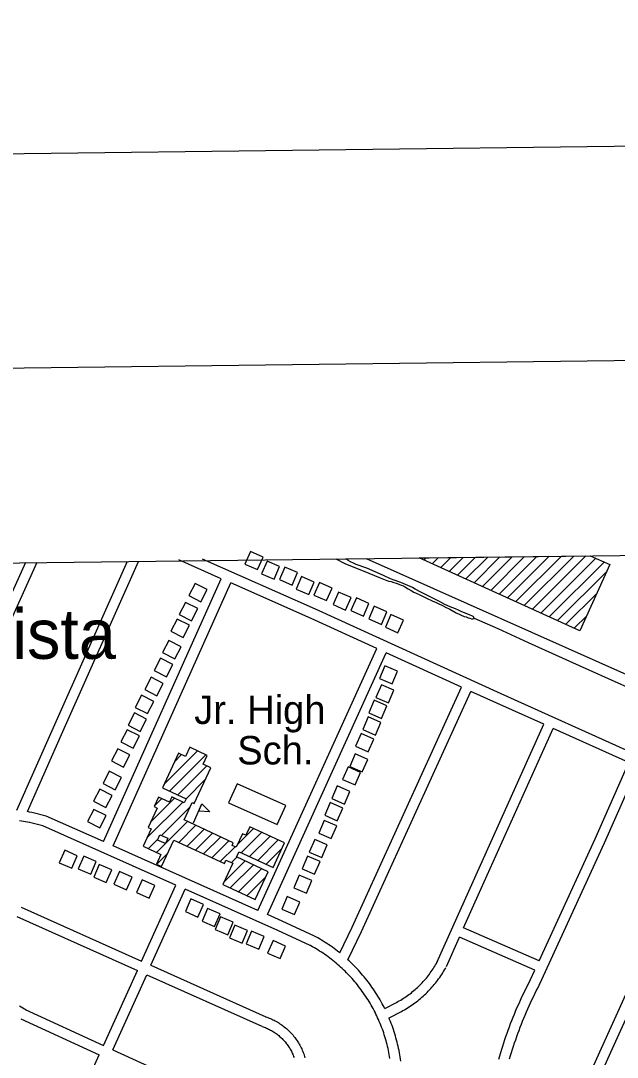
# Model space of a CAD drawing. Extents: x 3704301 to 3742427, y 506229 to 532009.
# Drawn here: x 3709792 to 3711530, y 528404 to 531426 of the extents above; entities that cross this region are included whole.
import ezdxf

# ---------------------------------------------------------------- set-up
doc = ezdxf.new("R2010")
doc.units = 0
for name, color, linetype in [('G-ANNO-NPLT', 7, 'Continuous'), ('V-ANNO-SYMB', 7, 'Continuous'), ('V-BLDG-IDEN', 7, 'Continuous'), ('V-BLDG-OTLN', 7, 'Continuous'), ('V-GRID-FRAM', 7, 'Continuous'), ('V-ROAD-CNTR', 7, 'Continuous'), ('V-TOPO-GNAM-IDEN', 7, 'Continuous'), ('V-TOPO-SHOR', 7, 'Continuous')]:
    doc.layers.add(name, color=color, linetype=linetype)

msp = doc.modelspace()

# ---------------------------------------------------------------- linework, layer by layer
at = {"layer": 'G-ANNO-NPLT'}
msp.add_lwpolyline([(3705179.5, 506812.7), (3741843.4, 507260.7), (3741548.1, 531425.5), (3704884.2, 530977.6)], close=True, dxfattribs=at)
at = {"layer": 'V-ANNO-SYMB'}
msp.add_lwpolyline([(3707921.8, 507471.3), (3741002.5, 507875.5), (3740722.5, 530790.4), (3707641.8, 530386.2), (3707921.8, 507471.3)], dxfattribs=at)
at = {"layer": 'V-BLDG-OTLN'}
for p, q in [((3710952.7, 529859.5), (3711451.3, 529865.6)), ((3711161.5, 529764.9), (3711259.8, 529863.3)), ((3711185.8, 529753.9), (3711295.6, 529863.7)), ((3711210.2, 529742.9), (3711331.4, 529864.2)), ((3711234.5, 529731.9), (3711367.2, 529864.6)), ((3711258.8, 529720.9), (3711403, 529865)), ((3711283.2, 529709.8), (3711438.8, 529865.5)), ((3710966.8, 529853.1), (3710973.5, 529859.8)), ((3710991.1, 529842.1), (3711009.3, 529860.2)), ((3711015.5, 529831.1), (3711045.1, 529860.7)), ((3711039.8, 529820.1), (3711080.8, 529861.1)), ((3711064.1, 529809), (3711116.6, 529861.5)), ((3711088.5, 529798), (3711152.4, 529862)), ((3711112.8, 529787), (3711188.2, 529862.4)), ((3711137.1, 529776), (3711224, 529862.8)), ((3711307.5, 529698.8), (3711467.1, 529858.4)), ((3711331.8, 529687.8), (3711491.4, 529847.4)), ((3711356.2, 529676.8), (3711499.3, 529819.9)), ((3711380.5, 529665.8), (3711470, 529755.3)), ((3711404.8, 529654.7), (3711440.8, 529690.7)), ((3710209.1, 529198.8), (3710307.1, 529296.8)), ((3710225.4, 529179.7), (3710331.3, 529285.6)), ((3710239.9, 529264.9), (3710260.9, 529286)), ((3710249.5, 529168.4), (3710334.2, 529253.1)), ((3710273.6, 529157.2), (3710330.5, 529214.1)), ((3710159.7, 529043.3), (3710264.2, 529147.8)), ((3710170.8, 529089.7), (3710240, 529159)), ((3710181, 529135.3), (3710203.5, 529157.8)), ((3710295.5, 529087.4), (3710320.1, 529142.1)), ((3710295.8, 529144), (3710299.7, 529148)), ((3710202.1, 529050.4), (3710285.4, 529133.6)), ((3710187.5, 529000.4), (3710278.1, 529091)), ((3710252.6, 529030.1), (3710302.2, 529079.8)), ((3710276.7, 529018.9), (3710326.4, 529068.5)), ((3710300.8, 529007.6), (3710350.5, 529057.3)), ((3710424.2, 529024.9), (3710470, 529070.8)), ((3710434.4, 528999.8), (3710494.1, 529059.5)), ((3710458.5, 528988.6), (3710518.3, 529048.3)), ((3710163.4, 529011.6), (3710191.7, 529039.9)), ((3710324.9, 528996.4), (3710374.6, 529046.1)), ((3710349.1, 528985.2), (3710398.7, 529034.8)), ((3710373.2, 528973.9), (3710416.5, 529017.2)), ((3710482.7, 528977.3), (3710542.4, 529037.1)), ((3710188.6, 528966.1), (3710219.1, 528996.6)), ((3710405.8, 528971.2), (3710421.8, 528987.2)), ((3710506.8, 528966.1), (3710552.9, 529012.3)), ((3710385, 528915), (3710446, 528976)), ((3710402.5, 528897.2), (3710470.1, 528964.8)), ((3710426.6, 528885.9), (3710494.2, 528953.5)), ((3710450.7, 528874.7), (3710507, 528930.9)), ((3710474.9, 528863.5), (3710476.2, 528864.8))]:
    msp.add_line(p, q, dxfattribs=at)
for points in [[(3710461.2, 529877.8), (3710445.2, 529841.2), (3710481.9, 529825.2), (3710497.9, 529861.8)], [(3710509.8, 529850.1), (3710493.8, 529813.4), (3710530.4, 529797.4), (3710546.4, 529834.1)], [(3710561.8, 529832.7), (3710545.8, 529796.1), (3710582.4, 529780.1), (3710598.5, 529816.7)], [(3710610.4, 529805), (3710594.3, 529768.3), (3710631, 529752.3), (3710647, 529789)], [(3710317.1, 529731.4), (3710335.5, 529766.9), (3710300, 529785.3), (3710281.6, 529749.8)], [(3710662.4, 529787.7), (3710646.4, 529751), (3710683, 529735), (3710699, 529771.7)], [(3710717.9, 529759.9), (3710701.9, 529723.3), (3710738.5, 529707.2), (3710754.5, 529743.9)], [(3710769.9, 529742.6), (3710753.9, 529705.9), (3710790.5, 529689.9), (3710806.6, 529726.6)], [(3710289.4, 529675.9), (3710307.7, 529711.5), (3710272.2, 529729.8), (3710253.8, 529694.3)], [(3710821.9, 529718.3), (3710805.9, 529681.6), (3710842.6, 529665.6), (3710858.6, 529702.3)], [(3710870.5, 529694), (3710854.5, 529657.4), (3710891.1, 529641.4), (3710907.1, 529678)], [(3710265.1, 529627.4), (3710283.5, 529662.9), (3710247.9, 529681.3), (3710229.6, 529645.7)], [(3710240.8, 529564.9), (3710259.2, 529600.5), (3710223.7, 529618.8), (3710205.3, 529583.3)], [(3710216.5, 529512.9), (3710234.9, 529548.4), (3710199.4, 529566.8), (3710181, 529531.3)], [(3710853.1, 529544.9), (3710837.1, 529508.2), (3710873.8, 529492.2), (3710889.8, 529528.9)], [(3710188.8, 529457.4), (3710207.2, 529493), (3710171.6, 529511.3), (3710153.3, 529475.8)], [(3710842.7, 529489.4), (3710826.7, 529452.7), (3710863.4, 529436.7), (3710879.4, 529473.4)], [(3710161, 529405.4), (3710179.4, 529440.9), (3710143.9, 529459.3), (3710125.5, 529423.8)], [(3710821.9, 529444.3), (3710805.9, 529407.6), (3710842.6, 529391.6), (3710858.6, 529428.3)], [(3710140.2, 529353.4), (3710158.6, 529388.9), (3710123.1, 529407.3), (3710104.7, 529371.7)], [(3710804.6, 529395.7), (3710788.6, 529359.1), (3710825.2, 529343.1), (3710841.2, 529379.7)], [(3710119.4, 529304.8), (3710137.8, 529340.3), (3710102.3, 529358.7), (3710083.9, 529323.2)], [(3710783.8, 529347.2), (3710767.8, 529310.5), (3710804.4, 529294.5), (3710820.4, 529331.2)], [(3710091.7, 529249.3), (3710110.1, 529284.9), (3710074.5, 529303.2), (3710056.1, 529267.7)], [(3710411.4, 529028.9), (3710267.8, 529095.8), (3710291.2, 529146.1), (3710297.5, 529143.2), (3710346.1, 529247.5), (3710323.4, 529258.1), (3710335.3, 529283.7), (3710284.7, 529307.2), (3710272.3, 529280.7), (3710251.7, 529290.3), (3710204.7, 529189.3), (3710273.8, 529157.1), (3710268.5, 529145.7), (3710232.3, 529162.6), (3710225.3, 529147.6), (3710193.6, 529162.4), (3710180.6, 529134.5), (3710189.7, 529130.3), (3710163.1, 529073.3), (3710171.8, 529069.2), (3710148.3, 529018.7), (3710200.5, 528994.4), (3710187.6, 528966.6), (3710202, 528959.9), (3710237.9, 529036.9), (3710385.3, 528968.3), (3710390, 528978.5), (3710410.2, 528969.1), (3710381.3, 528907.1), (3710475.4, 528863.2), (3710513.3, 528944.6), (3710421.1, 528987.6), (3710428.2, 529002.7), (3710527, 528956.7), (3710560.6, 529028.6), (3710459.3, 529075.8), (3710447.7, 529050.9), (3710438.3, 529055.3), (3710419.9, 529015.7), (3710407.9, 529021.2)], [(3710766.4, 529288.2), (3710750.4, 529251.6), (3710787.1, 529235.6), (3710803.1, 529272.2)], [(3710067.4, 529183.4), (3710085.8, 529219), (3710050.2, 529237.3), (3710031.9, 529201.8)], [(3710745.6, 529250.1), (3710729.6, 529213.4), (3710766.3, 529197.4), (3710782.3, 529234.1)], [(3710397.7, 529145), (3710539.4, 529082), (3710564.3, 529138.1), (3710422.6, 529201.1)], [(3710039.7, 529131.4), (3710058, 529166.9), (3710022.5, 529185.3), (3710004.1, 529149.8)], [(3710714.4, 529194.6), (3710698.4, 529157.9), (3710735.1, 529141.9), (3710751.1, 529178.6)], [(3710320.1, 529142.1), (3710342.7, 529119.3), (3710310.6, 529121.1)], [(3710693.6, 529146), (3710677.6, 529109.4), (3710714.2, 529093.4), (3710730.3, 529130)], [(3710022.3, 529072.4), (3710040.7, 529108), (3710005.2, 529126.3), (3709986.8, 529090.8)], [(3710676.3, 529094), (3710660.2, 529057.4), (3710696.9, 529041.3), (3710712.9, 529078)], [(3710196.9, 529052.5), (3710220.6, 529042.7), (3710214.1, 529027.2), (3710190.5, 529037)], [(3710648.5, 529038.5), (3710632.5, 529001.9), (3710669.2, 528985.9), (3710685.2, 529022.5)], [(3709920.2, 529007.3), (3709904.2, 528970.6), (3709940.8, 528954.6), (3709956.8, 528991.3)], [(3709975.7, 528990), (3709959.7, 528953.3), (3709996.3, 528937.3), (3710012.3, 528974)], [(3710627.7, 528990), (3710611.7, 528953.3), (3710648.3, 528937.3), (3710664.4, 528974)], [(3710020.8, 528965.7), (3710004.7, 528929), (3710041.4, 528913), (3710057.4, 528949.7)], [(3710079.7, 528944.9), (3710063.7, 528908.2), (3710100.4, 528892.2), (3710116.4, 528928.9)], [(3710603.4, 528934.5), (3710587.4, 528897.8), (3710624.1, 528881.8), (3710640.1, 528918.5)], [(3710145.6, 528920.6), (3710129.6, 528883.9), (3710166.3, 528867.9), (3710182.3, 528904.6)], [(3710568.7, 528872), (3710552.7, 528835.4), (3710589.4, 528819.4), (3710605.4, 528856)], [(3710287.8, 528865.1), (3710271.8, 528828.4), (3710308.5, 528812.4), (3710324.5, 528849.1)], [(3710336.4, 528837.4), (3710320.4, 528800.7), (3710357, 528784.7), (3710373, 528821.4)], [(3710374.5, 528813.1), (3710358.5, 528776.4), (3710395.2, 528760.4), (3710411.2, 528797.1)], [(3710416.1, 528788.8), (3710400.1, 528752.1), (3710436.8, 528736.1), (3710452.8, 528772.8)], [(3710464.7, 528771.5), (3710448.7, 528734.8), (3710485.3, 528718.8), (3710501.3, 528755.5)], [(3710527.1, 528743.7), (3710511.1, 528707.1), (3710547.8, 528691.1), (3710563.8, 528727.7)]]:
    msp.add_lwpolyline(points, close=True, dxfattribs=at)
for points in [[(3711451.3, 529865.6), (3711508.3, 529839.8)], [(3711508.3, 529839.8), (3711421.1, 529647.3), (3710952.7, 529859.5)]]:
    msp.add_lwpolyline(points, dxfattribs=at)
at = {"layer": 'V-GRID-FRAM'}
msp.add_lwpolyline([(3708355.7, 529827.8), (3740022.4, 530214.7), (3740252.5, 512033.3), (3708569.9, 511646.2), (3708355.7, 529827.8)], dxfattribs=at)
at = {"layer": 'V-ROAD-CNTR'}
for points in [[(3709613.4, 529346.2), (3709839.6, 529847.1)], [(3709624.1, 529442.8), (3709806.7, 529847.2)], [(3709780.6, 529124.3), (3709887.1, 529365.4), (3710103.1, 529850.3)], [(3709811.4, 529119.8), (3709914.5, 529353.3), (3710135.3, 529848.8)], [(3710376.2, 529798.8), (3710252.5, 529853.7)], [(3711575.4, 529290), (3711191.2, 529463.4), (3710650.7, 529709.9), (3710321.8, 529855.8)], [(3710033.5, 529032.2), (3710376.2, 529798.8)], [(3710060.9, 529020), (3710403.7, 529786.7)], [(3710829.3, 529595.5), (3710638.4, 529682.6), (3710403.7, 529786.7)], [(3710483.2, 528831.8), (3710829.3, 529595.5)], [(3710510.6, 528819.6), (3710856.6, 529583)], [(3711076.4, 529482.8), (3710856.6, 529583)], [(3710721.4, 528708.2), (3710757.6, 528782.9), (3711076.4, 529482.8)], [(3710744.9, 528688.1), (3710784.8, 528770.1), (3711103.7, 529470.3)], [(3711315.7, 529374.3), (3711178.8, 529436.1), (3711103.7, 529470.3)], [(3711004.7, 528680.2), (3711097.2, 528888.2), (3711315.7, 529374.3)], [(3711082.4, 528781.2), (3711124.6, 528876), (3711343, 529362)], [(3711563.3, 529262.6), (3711343, 529362)], [(3711302.2, 528684.8), (3711465.3, 529040.6), (3711563.3, 529262.6)], [(3711304.4, 528617.4), (3711492.7, 529028.3), (3711590.7, 529250.2)], [(3709824, 529117.4), (3709817.8, 529118.6), (3709811.4, 529119.8)], [(3710033.5, 529032.2), (3709866.5, 529106.7), (3709824.8, 529117.2)], [(3709818.2, 529088), (3709812.2, 529089.2), (3709806.3, 529090.2), (3709800.4, 529091.2), (3709794.5, 529092.2), (3709788.6, 529093)], [(3710243.7, 528905.7), (3709856.7, 529078.2), (3709817.4, 529088.1)], [(3711303.5, 528028.7), (3711483.5, 528430.5), (3711696.5, 528899.4), (3711769.8, 529061)], [(3711333.6, 528022.5), (3711510.9, 528418.1), (3711723.8, 528887), (3711797.1, 529048.6)], [(3710483.2, 528831.8), (3710060.9, 529020)], [(3710144.1, 528684.1), (3710243.7, 528905.7)], [(3710171.4, 528671.8), (3710271.1, 528893.5)], [(3710634.9, 528729.8), (3710541, 528773.3), (3710271.1, 528893.5)], [(3709793.4, 528841.6), (3710144.1, 528684.1)], [(3709781.1, 528814.3), (3710131.8, 528656.7)], [(3710647.5, 528757.1), (3710553.4, 528800.6), (3710510.6, 528819.6)], [(3711302.2, 528684.8), (3711082.4, 528781.2)], [(3710721.4, 528708.2), (3710715.2, 528713.1), (3710710.1, 528716.9), (3710705, 528720.7), (3710699.9, 528724.4), (3710694.7, 528728.1), (3710689.5, 528731.7), (3710684.3, 528735.2), (3710678.9, 528738.6), (3710673.6, 528742), (3710668.2, 528745.3), (3710662.7, 528748.5), (3710657.3, 528751.7), (3710651.7, 528754.8), (3710648.3, 528756.6)], [(3711032.2, 528668), (3711070.3, 528753.8)], [(3711289.7, 528657.5), (3711070.3, 528753.8)], [(3710867.7, 528399.8), (3710866.8, 528405.6), (3710865.7, 528411.5), (3710864.6, 528417.3), (3710863.5, 528423.1), (3710862.2, 528428.9), (3710860.9, 528434.7), (3710859.4, 528440.5), (3710858, 528446.3), (3710856.4, 528452), (3710854.8, 528457.7), (3710853.1, 528463.4), (3710851.3, 528469), (3710849.4, 528474.7), (3710847.5, 528480.3), (3710845.5, 528485.9), (3710843.4, 528491.5), (3710841.3, 528497), (3710839, 528502.5), (3710836.7, 528508), (3710834.4, 528513.4), (3710831.9, 528518.8), (3710829.4, 528524.2), (3710826.9, 528529.6), (3710824.2, 528534.9), (3710821.5, 528540.2), (3710818.7, 528545.4), (3710815.9, 528550.6), (3710813, 528555.8), (3710810, 528560.9), (3710806.9, 528566), (3710803.8, 528571.1), (3710800.6, 528576.1), (3710797.4, 528581.1), (3710794, 528586), (3710790.7, 528590.9), (3710787.2, 528595.7), (3710783.7, 528600.5), (3710780.2, 528605.3), (3710776.5, 528610), (3710772.8, 528614.6), (3710769.1, 528619.2), (3710765.3, 528623.8), (3710761.4, 528628.3), (3710757.5, 528632.8), (3710753.5, 528637.2), (3710749.5, 528641.5), (3710745.4, 528645.8), (3710741.2, 528650.1), (3710737, 528654.2), (3710732.7, 528658.4), (3710728.4, 528662.5), (3710724.1, 528666.5), (3710719.6, 528670.4), (3710715.2, 528674.4), (3710710.6, 528678.2), (3710706.1, 528682), (3710701.4, 528685.7), (3710696.8, 528689.4), (3710692.1, 528693), (3710687.3, 528696.5), (3710682.5, 528700), (3710677.6, 528703.4), (3710672.7, 528706.8), (3710667.8, 528710.1), (3710662.8, 528713.3), (3710657.8, 528716.5), (3710652.7, 528719.6), (3710647.6, 528722.6), (3710642.5, 528725.6), (3710637.2, 528728.5), (3710634, 528730.3)], [(3710852.5, 528545.5), (3710848.1, 528554.1), (3710845.1, 528559.7), (3710842.1, 528565.2), (3710839, 528570.7), (3710835.8, 528576.2), (3710832.5, 528581.6), (3710829.2, 528587), (3710825.8, 528592.4), (3710822.4, 528597.7), (3710818.8, 528602.9), (3710815.2, 528608.1), (3710811.6, 528613.3), (3710807.8, 528618.4), (3710804, 528623.4), (3710800.2, 528628.5), (3710796.2, 528633.4), (3710792.2, 528638.3), (3710788.2, 528643.2), (3710784.1, 528648), (3710779.9, 528652.7), (3710775.6, 528657.4), (3710771.3, 528662.1), (3710766.9, 528666.7), (3710762.5, 528671.2), (3710758, 528675.6), (3710753.5, 528680.1), (3710748.9, 528684.4), (3710744.9, 528688.1)], [(3710033.4, 528438.1), (3710103.7, 528594.3), (3710131.8, 528656.7)], [(3710171.4, 528671.8), (3710506.3, 528521.3)], [(3710852.5, 528545.5), (3710886.8, 528563.5), (3710890.9, 528565.8), (3710895, 528568.1), (3710899.1, 528570.5), (3710903.1, 528573), (3710907.1, 528575.5), (3710911, 528578.1), (3710914.9, 528580.7), (3710918.8, 528583.4), (3710922.6, 528586.2), (3710926.4, 528589), (3710930.1, 528591.9), (3710933.7, 528594.9), (3710937.4, 528597.9), (3710940.9, 528601), (3710944.5, 528604.1), (3710947.9, 528607.3), (3710951.4, 528610.5), (3710954.7, 528613.8), (3710958, 528617.2), (3710961.3, 528620.6), (3710964.5, 528624.1), (3710967.7, 528627.6), (3710970.8, 528631.1), (3710973.8, 528634.7), (3710976.8, 528638.4), (3710979.7, 528642.1), (3710982.5, 528645.8), (3710985.3, 528649.6), (3710988.1, 528653.5), (3710990.7, 528657.4), (3710993.3, 528661.3), (3710995.9, 528665.3), (3710998.4, 528669.3), (3711000.8, 528673.3), (3711003.1, 528677.4), (3711006.3, 528683.1)], [(3710865, 528518.2), (3710901, 528537.1), (3710905.5, 528539.6), (3710910.1, 528542.1), (3710914.5, 528544.8), (3710919, 528547.5), (3710923.4, 528550.3), (3710927.7, 528553.1), (3710932, 528556.1), (3710936.2, 528559), (3710940.5, 528562.1), (3710944.6, 528565.2), (3710948.7, 528568.4), (3710952.8, 528571.7), (3710956.7, 528575), (3710960.7, 528578.4), (3710964.6, 528581.9), (3710968.4, 528585.4), (3710972.2, 528588.9), (3710975.9, 528592.6), (3710979.5, 528596.3), (3710983.1, 528600), (3710986.7, 528603.8), (3710990.1, 528607.7), (3710993.6, 528611.6), (3710996.9, 528615.6), (3711000.2, 528619.6), (3711003.4, 528623.7), (3711006.5, 528627.9), (3711009.6, 528632), (3711012.6, 528636.3), (3711015.6, 528640.6), (3711018.5, 528644.9), (3711021.3, 528649.3), (3711024, 528653.7), (3711026.7, 528658.2), (3711029.3, 528662.7), (3711030.6, 528665.2)], [(3711277.1, 528629.9), (3711289.7, 528657.5)], [(3710060.6, 528425.5), (3710131.1, 528582), (3710159.1, 528644.4)], [(3710159.1, 528644.4), (3710494, 528493.9)], [(3711184.8, 528398.4), (3711187.6, 528407.9), (3711190.4, 528417.4), (3711193.3, 528426.8), (3711196.2, 528436.3), (3711199.3, 528445.7), (3711202.4, 528455.1), (3711205.6, 528464.5), (3711208.9, 528473.8), (3711212.2, 528483.1), (3711215.7, 528492.4), (3711219.2, 528501.7), (3711222.7, 528510.9), (3711226.4, 528520.1), (3711230.1, 528529.3), (3711233.9, 528538.4), (3711237.8, 528547.5), (3711241.8, 528556.6), (3711245.8, 528565.6), (3711249.9, 528574.6), (3711254.1, 528583.6), (3711258.3, 528592.5), (3711262.7, 528601.4), (3711267, 528610.3), (3711271.5, 528619.1), (3711276, 528627.9), (3711277.5, 528630.6)], [(3711216.4, 528399.5), (3711219.1, 528408.7), (3711221.9, 528418), (3711224.8, 528427.2), (3711227.8, 528436.4), (3711230.8, 528445.5), (3711234, 528454.7), (3711237.1, 528463.8), (3711240.4, 528472.8), (3711243.8, 528481.9), (3711247.2, 528490.9), (3711250.7, 528499.9), (3711254.2, 528508.9), (3711257.9, 528517.8), (3711261.6, 528526.7), (3711265.4, 528535.6), (3711269.2, 528544.5), (3711273.2, 528553.3), (3711277.2, 528562.1), (3711281.2, 528570.8), (3711285.4, 528579.5), (3711289.6, 528588.2), (3711293.9, 528596.9), (3711298.2, 528605.5), (3711302.7, 528614.1), (3711304, 528616.7)], [(3709788.8, 528553.6), (3709793.3, 528550.7), (3709797.9, 528547.8), (3709802.6, 528544.9), (3709806.6, 528542.5)], [(3709805.2, 528543.3), (3710033.4, 528438.1)], [(3709792.6, 528516), (3710021, 528410.7)], [(3710505, 528521.8), (3710508.6, 528520.6), (3710512.3, 528519.3), (3710515.9, 528517.8), (3710519.6, 528516.3), (3710523.2, 528514.7), (3710526.7, 528513.1), (3710530.2, 528511.3), (3710533.7, 528509.5), (3710537.2, 528507.6), (3710540.6, 528505.6), (3710543.9, 528503.6), (3710547.2, 528501.5), (3710550.5, 528499.3), (3710553.7, 528497), (3710556.9, 528494.7), (3710560, 528492.2), (3710563, 528489.8), (3710566, 528487.2), (3710569, 528484.6), (3710571.8, 528481.9), (3710574.7, 528479.2), (3710577.4, 528476.4), (3710580.1, 528473.5), (3710582.7, 528470.6), (3710585.3, 528467.6), (3710587.8, 528464.6), (3710590.2, 528461.5), (3710592.6, 528458.4), (3710594.9, 528455.2), (3710597.1, 528451.9), (3710599.3, 528448.6), (3710601.3, 528445.3), (3710603.3, 528441.9), (3710605.3, 528438.5), (3710607.1, 528435), (3710608.9, 528431.5), (3710610.6, 528427.9), (3710612.2, 528424.3), (3710613.7, 528420.7), (3710615.2, 528417.1), (3710616.5, 528413.4), (3710617.8, 528409.7), (3710619, 528405.9), (3710620.1, 528402.2)], [(3710899.2, 528392), (3710898.3, 528398.2), (3710897.4, 528404.4), (3710896.4, 528410.7), (3710895.3, 528416.9), (3710894.1, 528423.1), (3710892.8, 528429.3), (3710891.5, 528435.5), (3710890, 528441.7), (3710888.5, 528447.8), (3710887, 528453.9), (3710885.3, 528460.1), (3710883.6, 528466.1), (3710881.7, 528472.2), (3710879.8, 528478.2), (3710877.8, 528484.3), (3710875.8, 528490.2), (3710873.7, 528496.2), (3710871.4, 528502.1), (3710869.2, 528508), (3710866.8, 528513.9), (3710865, 528518.2)], [(3710495.4, 528493.4), (3710498.6, 528492.3), (3710501.7, 528491.2), (3710504.7, 528490), (3710507.8, 528488.7), (3710510.7, 528487.4), (3710513.7, 528486), (3710516.6, 528484.6), (3710519.5, 528483.1), (3710522.4, 528481.5), (3710525.2, 528479.9), (3710528, 528478.2), (3710530.7, 528476.4), (3710533.4, 528474.6), (3710536.1, 528472.7), (3710538.7, 528470.7), (3710541.3, 528468.7), (3710543.9, 528466.7), (3710546.3, 528464.6), (3710548.8, 528462.4), (3710551.2, 528460.2), (3710553.5, 528457.9), (3710555.8, 528455.6), (3710558, 528453.2), (3710560.2, 528450.8), (3710562.4, 528448.3), (3710564.4, 528445.8), (3710566.5, 528443.2), (3710568.4, 528440.6), (3710570.3, 528438), (3710572.2, 528435.3), (3710573.9, 528432.5), (3710575.7, 528429.7), (3710577.3, 528426.9), (3710578.9, 528424.1), (3710580.5, 528421.2), (3710581.9, 528418.3), (3710583.3, 528415.3), (3710584.7, 528412.4), (3710585.9, 528409.4), (3710587.1, 528406.3), (3710588.3, 528403.3)], [(3710060.6, 528425.5), (3710232.3, 528346.4)], [(3709921.6, 528189.9), (3710021, 528410.7)]]:
    msp.add_lwpolyline(points, dxfattribs=at)
at = {"layer": 'V-TOPO-SHOR'}
for points in [[(3710709.7, 529856.6), (3710736.7, 529843.2), (3710806.4, 529814.9), (3710839.2, 529801.8), (3710858.8, 529794), (3710864, 529792.1), (3710871, 529790.3), (3710878.8, 529788)], [(3711112.6, 529683.8), (3711112.6, 529684), (3711112.4, 529685.2), (3711112.2, 529686.1), (3711111.6, 529687), (3711109.9, 529688.7), (3711106, 529690.7), (3711101, 529692.5), (3711075.5, 529703.1), (3711067.4, 529707), (3711058.6, 529710.9), (3711050.8, 529714), (3711043, 529717.2), (3711027.7, 529723.8), (3711018.7, 529728.1), (3711012.2, 529732.2), (3710957.2, 529759.9), (3710941.4, 529768.4), (3710932.9, 529773.3), (3710899.4, 529787.6), (3710880.1, 529794.6), (3710869.6, 529798.8), (3710848.7, 529808.2), (3710800.7, 529829.7), (3710769.7, 529840.2), (3710761.1, 529844.1), (3710752.6, 529848.3), (3710746.1, 529851.8), (3710740.8, 529855.4), (3710739.1, 529856.9)], [(3710798.5, 529857.6), (3711574.3, 529511.7)], [(3710878.8, 529788), (3710886.2, 529785.4), (3710893.7, 529782.6), (3710900.4, 529780.1), (3710906.7, 529777.6), (3710913.4, 529774), (3710921.2, 529769.4), (3710929.7, 529764.1), (3710937.4, 529759.9), (3710944.3, 529756.8), (3710952.5, 529753.2), (3710960.7, 529749), (3710972.4, 529743.1), (3710992.5, 529733.7), (3711000.3, 529730.3), (3711010.4, 529725.7), (3711020.7, 529720.7), (3711030, 529716.3), (3711042.5, 529710), (3711060.5, 529699.6), (3711083.9, 529689.1), (3711089.8, 529687.2), (3711095.4, 529685), (3711100.1, 529683.4), (3711105.2, 529682.2), (3711109.3, 529682), (3711111.8, 529682.4), (3711112.6, 529683.2), (3711112.6, 529683.8)], [(3711112.6, 529683.8), (3711182.1, 529653.5), (3711270, 529612.4), (3711419.3, 529545.3), (3711540, 529490.9), (3711628.1, 529452.8)]]:
    msp.add_lwpolyline(points, dxfattribs=at)

# ---------------------------------------------------------------- texts
at = {"layer": 'V-BLDG-IDEN'}
for s, p in [('Jr. High', (3710297.5, 529375.2)), ('Sch.', (3710422.8, 529257.3))]:
    msp.add_text(s, height=83, dxfattribs=at).set_placement(p)
at = {"layer": 'V-TOPO-GNAM-IDEN'}
msp.add_text('Chalmette Vista', height=145, dxfattribs=at).set_placement((3708700.6, 529565.2))

doc.saveas('drawing.dxf')
